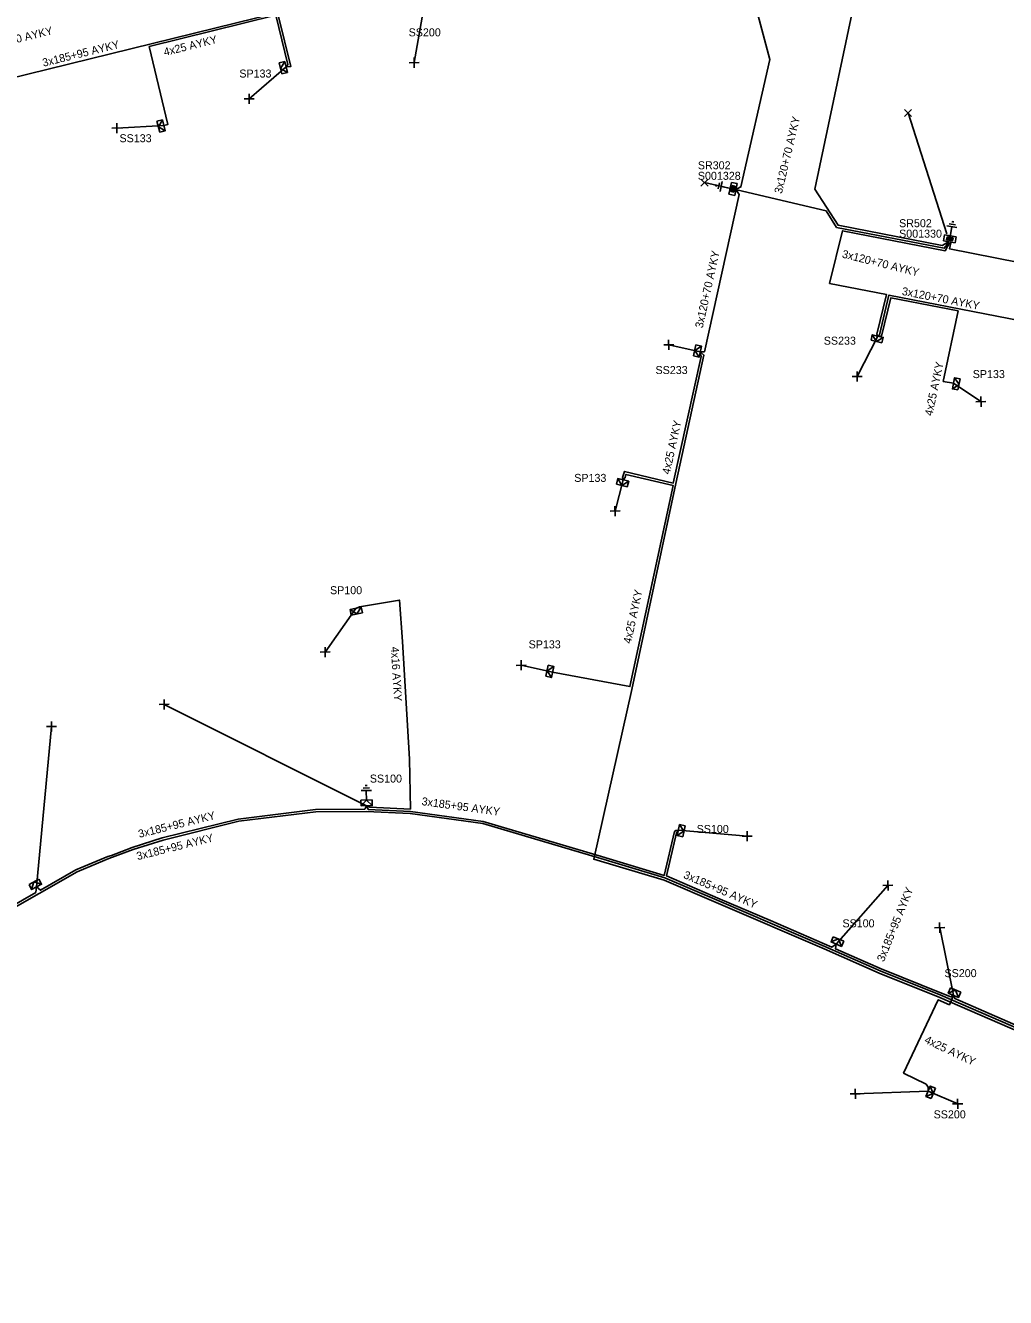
# Model space of a CAD drawing. Extents: x -762500 to -761285, y -1155006 to -1154135.
# Drawn here: x -762207.7 to -762085.9, y -1154817.7 to -1154659.6 of the extents above; entities that cross this region are included whole.
import ezdxf

# ---------------------------------------------------------------- set-up
doc = ezdxf.new("R2010")
doc.units = 0
for name, color, linetype in [('Vrstva 15', 7, 'Continuous'), ('Vrstva 28', 7, 'Continuous'), ('Vrstva 29', 7, 'Continuous'), ('Vrstva 30', 7, 'Continuous'), ('Vrstva 31', 7, 'Continuous'), ('Vrstva 33', 7, 'Continuous'), ('Vrstva 34', 7, 'Continuous'), ('Vrstva 5', 7, 'Continuous'), ('Vrstva 59', 7, 'Continuous'), ('Vrstva 6', 7, 'Continuous')]:
    doc.layers.add(name, color=color, linetype=linetype)

msp = doc.modelspace()

# ---------------------------------------------------------------- linework, layer by layer
at = {"layer": 'Vrstva 15'}
for points in [[(-762121.928, -1154679.632), (-762121.901, -1154679.502)], [(-762121.901, -1154679.502), (-762121.874, -1154679.376)], [(-762121.672, -1154679.943), (-762121.509, -1154679.172)], [(-762121.419, -1154680.243), (-762121.159, -1154679.02)], [(-762120.067, -1154679.891), (-762121.289, -1154679.632)], [(-762093.221, -1154684.529), (-762091.99, -1154684.746)], [(-762092.93, -1154684.266), (-762092.155, -1154684.402)], [(-762092.823, -1154685.869), (-762092.606, -1154684.638)], [(-762092.628, -1154683.999), (-762092.497, -1154684.022)], [(-762092.497, -1154684.022), (-762092.371, -1154684.044)], [(-762165.767, -1154754.397), (-762164.979, -1154754.383)], [(-762165.521, -1154754.078), (-762165.388, -1154754.075)], [(-762165.388, -1154754.075), (-762165.26, -1154754.073)], [(-762166.002, -1154754.711), (-762164.752, -1154754.689)], [(-762165.355, -1154755.95), (-762165.377, -1154754.7)]]:
    msp.add_lwpolyline(points, dxfattribs=at)
at = {"layer": 'Vrstva 28'}
for points in [[(-762120.015, -1154679.133), (-762120.327, -1154680.6)], [(-762119.907, -1154679.536), (-762120.062, -1154680.264)], [(-762120.062, -1154680.264), (-762119.692, -1154680.343)], [(-762119.281, -1154679.289), (-762120.015, -1154679.133)], [(-762119.871, -1154679.592), (-762120.006, -1154680.228)], [(-762120.006, -1154680.228), (-762119.729, -1154680.287)], [(-762119.835, -1154679.649), (-762119.95, -1154680.192)], [(-762119.95, -1154680.192), (-762119.765, -1154680.231)], [(-762119.538, -1154679.615), (-762119.907, -1154679.536)], [(-762119.798, -1154679.705), (-762119.894, -1154680.155)], [(-762119.894, -1154680.155), (-762119.802, -1154680.175)], [(-762119.594, -1154679.651), (-762119.871, -1154679.592)], [(-762119.761, -1154679.755), (-762119.839, -1154680.125)], [(-762119.65, -1154679.688), (-762119.835, -1154679.649)], [(-762119.802, -1154680.175), (-762119.706, -1154679.724)], [(-762119.706, -1154679.724), (-762119.798, -1154679.705)], [(-762119.765, -1154680.231), (-762119.65, -1154679.688)], [(-762119.729, -1154680.287), (-762119.594, -1154679.651)], [(-762119.692, -1154680.343), (-762119.538, -1154679.615)], [(-762119.593, -1154680.756), (-762119.281, -1154679.289)], [(-762120.327, -1154680.6), (-762119.593, -1154680.756)], [(-762093.541, -1154685.635), (-762093.671, -1154686.373)], [(-762093.671, -1154686.373), (-762092.194, -1154686.634)], [(-762092.064, -1154685.895), (-762093.541, -1154685.635)], [(-762093.196, -1154685.887), (-762093.261, -1154686.26)], [(-762093.261, -1154686.26), (-762092.528, -1154686.389)], [(-762093.157, -1154685.942), (-762093.206, -1154686.221)], [(-762093.206, -1154686.221), (-762092.567, -1154686.334)], [(-762092.463, -1154686.017), (-762093.196, -1154685.887)], [(-762092.517, -1154686.055), (-762093.157, -1154685.942)], [(-762093.119, -1154685.997), (-762093.152, -1154686.183)], [(-762093.152, -1154686.183), (-762092.605, -1154686.279)], [(-762092.572, -1154686.093), (-762093.119, -1154685.997)], [(-762093.081, -1154686.052), (-762093.097, -1154686.145)], [(-762093.097, -1154686.145), (-762092.643, -1154686.225)], [(-762092.627, -1154686.132), (-762093.081, -1154686.052)], [(-762092.676, -1154686.171), (-762093.048, -1154686.105)], [(-762092.643, -1154686.225), (-762092.627, -1154686.132)], [(-762092.605, -1154686.279), (-762092.572, -1154686.093)], [(-762092.567, -1154686.334), (-762092.517, -1154686.055)], [(-762092.528, -1154686.389), (-762092.463, -1154686.017)], [(-762092.194, -1154686.634), (-762092.064, -1154685.895)]]:
    msp.add_lwpolyline(points, dxfattribs=at)
at = {"layer": 'Vrstva 31'}
for points in [[(-762176.199, -1154664.278), (-762175.52, -1154664.108), (-762175.182, -1154665.467), (-762175.861, -1154665.636)], [(-762176.199, -1154664.278), (-762175.861, -1154665.636)], [(-762176.03, -1154664.957), (-762175.52, -1154664.108)], [(-762176.03, -1154664.957), (-762175.182, -1154665.467)], [(-762191.39, -1154671.528), (-762190.711, -1154671.358), (-762190.372, -1154672.717), (-762191.051, -1154672.886)], [(-762191.39, -1154671.528), (-762191.051, -1154672.886)], [(-762191.221, -1154672.207), (-762190.711, -1154671.358)], [(-762191.221, -1154672.207), (-762190.372, -1154672.717)], [(-762102.662, -1154698.755), (-762102.505, -1154698.073), (-762101.141, -1154698.388), (-762101.298, -1154699.07)], [(-762102.662, -1154698.755), (-762101.298, -1154699.07)], [(-762101.98, -1154698.912), (-762102.505, -1154698.073)], [(-762101.98, -1154698.912), (-762101.141, -1154698.388)], [(-762124.429, -1154699.337), (-762124.72, -1154700.706)], [(-762124.429, -1154699.337), (-762123.744, -1154699.483), (-762124.035, -1154700.852), (-762124.72, -1154700.706)], [(-762124.574, -1154700.022), (-762123.744, -1154699.483)], [(-762124.574, -1154700.022), (-762124.035, -1154700.852)], [(-762091.856, -1154704.923), (-762092.543, -1154704.79), (-762092.276, -1154703.416), (-762091.589, -1154703.549)], [(-762091.723, -1154704.236), (-762092.276, -1154703.416)], [(-762091.856, -1154704.923), (-762091.589, -1154703.549)], [(-762091.723, -1154704.236), (-762092.543, -1154704.79)], [(-762134.301, -1154716.62), (-762134.132, -1154715.941), (-762132.773, -1154716.279), (-762132.943, -1154716.958)], [(-762134.301, -1154716.62), (-762132.943, -1154716.958)], [(-762133.622, -1154716.789), (-762134.132, -1154715.941)], [(-762133.622, -1154716.789), (-762132.773, -1154716.279)], [(-762167.242, -1154732.901), (-762167.388, -1154732.216), (-762166.018, -1154731.925), (-762165.873, -1154732.61)], [(-762166.557, -1154732.756), (-762167.388, -1154732.216)], [(-762166.557, -1154732.756), (-762166.018, -1154731.925)], [(-762167.242, -1154732.901), (-762165.873, -1154732.61)], [(-762142.769, -1154739.147), (-762143.06, -1154740.516)], [(-762142.769, -1154739.147), (-762142.084, -1154739.293), (-762142.375, -1154740.662), (-762143.06, -1154740.516)], [(-762142.915, -1154739.832), (-762142.084, -1154739.293)], [(-762142.915, -1154739.832), (-762142.375, -1154740.662)], [(-762164.649, -1154755.878), (-762166.049, -1154755.902)], [(-762164.649, -1154755.878), (-762164.637, -1154756.578), (-762166.037, -1154756.602), (-762166.049, -1154755.902)], [(-762165.349, -1154755.89), (-762166.037, -1154756.602)], [(-762165.349, -1154755.89), (-762164.637, -1154756.578)], [(-762126.051, -1154760.454), (-762126.736, -1154760.308), (-762126.445, -1154758.939), (-762125.76, -1154759.084)], [(-762125.906, -1154759.769), (-762126.445, -1154758.939)], [(-762126.051, -1154760.454), (-762125.76, -1154759.084)], [(-762125.906, -1154759.769), (-762126.736, -1154760.308)], [(-762206.059, -1154765.742), (-762207.295, -1154766.399)], [(-762206.059, -1154765.742), (-762205.73, -1154766.36), (-762206.966, -1154767.017), (-762207.295, -1154766.399)], [(-762206.677, -1154766.07), (-762206.966, -1154767.017)], [(-762206.677, -1154766.07), (-762205.73, -1154766.36)], [(-762106.059, -1154773.43), (-762106.333, -1154774.074), (-762107.621, -1154773.527), (-762107.348, -1154772.883)], [(-762106.704, -1154773.157), (-762107.621, -1154773.527)], [(-762106.059, -1154773.43), (-762107.348, -1154772.883)], [(-762106.704, -1154773.157), (-762106.333, -1154774.074)], [(-762091.499, -1154779.78), (-762091.772, -1154780.424), (-762093.061, -1154779.877), (-762092.788, -1154779.233)], [(-762092.143, -1154779.507), (-762093.061, -1154779.877)], [(-762091.499, -1154779.78), (-762092.788, -1154779.233)], [(-762092.143, -1154779.507), (-762091.772, -1154780.424)], [(-762095.2, -1154793.001), (-762095.845, -1154792.727), (-762095.298, -1154791.439), (-762094.653, -1154791.712)], [(-762094.927, -1154792.357), (-762095.845, -1154792.727)], [(-762094.927, -1154792.357), (-762095.298, -1154791.439)], [(-762095.2, -1154793.001), (-762094.653, -1154791.712)]]:
    msp.add_lwpolyline(points, dxfattribs=at)
at = {"layer": 'Vrstva 34'}
for points in [[(-762160.065, -1154664.261), (-762158.815, -1154664.239)], [(-762159.429, -1154664.875), (-762159.451, -1154663.625)], [(-762180.565, -1154668.761), (-762179.315, -1154668.739)], [(-762179.929, -1154669.375), (-762179.951, -1154668.125)], [(-762098.502, -1154670.058), (-762097.618, -1154670.942)], [(-762098.502, -1154670.942), (-762097.618, -1154670.058)], [(-762197.005, -1154672.391), (-762195.755, -1154672.369)], [(-762196.369, -1154673.005), (-762196.391, -1154671.755)], [(-762123.792, -1154678.718), (-762122.908, -1154679.602)], [(-762123.792, -1154679.602), (-762122.908, -1154678.718)], [(-762128.425, -1154699.321), (-762127.175, -1154699.299)], [(-762127.789, -1154699.935), (-762127.811, -1154698.685)], [(-762105.005, -1154703.261), (-762103.755, -1154703.239)], [(-762104.369, -1154703.875), (-762104.391, -1154702.625)], [(-762089.625, -1154706.391), (-762088.375, -1154706.369)], [(-762088.989, -1154707.005), (-762089.011, -1154705.755)], [(-762134.459, -1154720.605), (-762134.481, -1154719.355)], [(-762135.095, -1154719.991), (-762133.845, -1154719.969)], [(-762170.489, -1154738.125), (-762170.511, -1154736.875)], [(-762171.125, -1154737.511), (-762169.875, -1154737.489)], [(-762146.129, -1154739.765), (-762146.151, -1154738.515)], [(-762146.765, -1154739.151), (-762145.515, -1154739.129)], [(-762190.489, -1154744.625), (-762190.511, -1154743.375)], [(-762191.125, -1154744.011), (-762189.875, -1154743.989)], [(-762205.125, -1154746.761), (-762203.875, -1154746.739)], [(-762204.489, -1154747.375), (-762204.511, -1154746.125)], [(-762118.685, -1154760.391), (-762117.435, -1154760.369)], [(-762118.049, -1154761.005), (-762118.071, -1154759.755)], [(-762101.185, -1154766.511), (-762099.935, -1154766.489)], [(-762100.549, -1154767.125), (-762100.571, -1154765.875)], [(-762094.755, -1154771.761), (-762093.505, -1154771.739)], [(-762094.119, -1154772.375), (-762094.141, -1154771.125)], [(-762105.245, -1154792.411), (-762103.995, -1154792.389)], [(-762104.609, -1154793.025), (-762104.631, -1154791.775)], [(-762092.515, -1154793.661), (-762091.265, -1154793.639)], [(-762091.879, -1154794.275), (-762091.901, -1154793.025)]]:
    msp.add_lwpolyline(points, dxfattribs=at)
at = {"layer": 'Vrstva 5'}
for points in [[(-762018.03, -1154646.45), (-762017.58, -1154646.23), (-762016.49, -1154646.47), (-762014.67, -1154637.34), (-762032.87, -1154633.54), (-762058.42, -1154628.52), (-762100.97, -1154638.95), (-762109.63, -1154679.98), (-762106.75, -1154684.45), (-762093.8, -1154686.97), (-762093.14, -1154686.59)], [(-762139.3, -1154653.19), (-762139.13, -1154652.68), (-762140.12, -1154649.04), (-762120.48, -1154644.08), (-762115.24, -1154663.87), (-762118.83, -1154679.7), (-762119.29, -1154679.92)], [(-762223.4, -1154669.64), (-762222.98, -1154669.48), (-762140.4, -1154649.15), (-762139.3, -1154653.19)], [(-762139.3, -1154653.19), (-762139.7, -1154652.86), (-762140.61, -1154649.51), (-762159.19, -1154654.08), (-762158.25, -1154657.62), (-762158.33, -1154657.9), (-762158.54, -1154657.7), (-762159.49, -1154654.13), (-762176.33, -1154658.33), (-762174.77, -1154664.73), (-762175.35, -1154664.79), (-762175.14, -1154664.47), (-762176.64, -1154658.36), (-762192.36, -1154662.25), (-762190.04, -1154671.92), (-762190.54, -1154672.04)], [(-762123.89, -1154700.17), (-762123.37, -1154700.17), (-762119.06, -1154680.65), (-762119.34, -1154680.18)], [(-762119.32, -1154680.05), (-762108.25, -1154682.68), (-762106.94, -1154684.72), (-762093.57, -1154687.32), (-762093.01, -1154686.61)], [(-762092.89, -1154686.64), (-762093.45, -1154687.65), (-762106.2, -1154685.14), (-762107.82, -1154691.68), (-762100.72, -1154693.07), (-762101.93, -1154697.99), (-762101.82, -1154698.24)], [(-762092.76, -1154686.66), (-762092.9, -1154687.39), (-762055.52, -1154694.77), (-762054.12, -1154687.55), (-762054.84, -1154687.45)], [(-762101.82, -1154698.24), (-762101.62, -1154698.07), (-762100.44, -1154693.13), (-762079.55, -1154697.2), (-762078.36, -1154697.42), (-762078.23, -1154698.37), (-762077.81, -1154697.52), (-762019.05, -1154708.75), (-762020.51, -1154715.85), (-762021.06, -1154716.05)], [(-762101.82, -1154698.24), (-762101.35, -1154698.23), (-762100.21, -1154693.48), (-762091.84, -1154695.11), (-762093.69, -1154703.86), (-762092.4, -1154704.1)], [(-762123.89, -1154700.17), (-762123.78, -1154700.77), (-762127.23, -1154716.5), (-762133.31, -1154715.06), (-762133.54, -1154715.82), (-762133.45, -1154716.11), (-762133.22, -1154715.82), (-762133.11, -1154715.42), (-762127.26, -1154716.79), (-762132.63, -1154741.8), (-762142.23, -1154739.98)], [(-762005.47, -1154815.51), (-762005.9, -1154815.54), (-762006.91, -1154817.72), (-762027.5, -1154808.79), (-762050.51, -1154798.85), (-762079.21, -1154786.89), (-762094.1, -1154780.44), (-762101.63, -1154777.4), (-762108.5, -1154774.39), (-762121.62, -1154768.73), (-762128.38, -1154765.83), (-762137.12, -1154763.24), (-762132.4, -1154742.15), (-762126.9, -1154716.57), (-762123.43, -1154700.6), (-762123.89, -1154700.17)], [(-762165.34, -1154756.59), (-762164.94, -1154756.76), (-762159.89, -1154757.01), (-762160.03, -1154750.83), (-762160.9, -1154736.18), (-762161.27, -1154731.03), (-762166.22, -1154731.88), (-762166.7, -1154732.07)], [(-762234.41, -1154785.99), (-762234.08, -1154785.6), (-762232.76, -1154782.95), (-762217.81, -1154773.87), (-762206.44, -1154767.37), (-762206.35, -1154766.69), (-762205.87, -1154767.1), (-762201.48, -1154764.57), (-762197.5, -1154762.89), (-762197.06, -1154762.77), (-762194.48, -1154761.79), (-762190.73, -1154760.6), (-762181.3, -1154758.26), (-762171.71, -1154757.08), (-762165.58, -1154757.01), (-762165.34, -1154756.59)], [(-762217.64, -1154774.11), (-762206.02, -1154767.5), (-762201.33, -1154764.82), (-762197.37, -1154763.14), (-762194.37, -1154762.05), (-762190.63, -1154760.87), (-762181.23, -1154758.53), (-762171.67, -1154757.36), (-762165.37, -1154757.31), (-762159.93, -1154757.58), (-762150.92, -1154758.82), (-762136.22, -1154763.17), (-762128.28, -1154765.54), (-762121.5, -1154768.45), (-762108.38, -1154774.11), (-762101.51, -1154777.12), (-762093.99, -1154780.16), (-762079.09, -1154786.61)], [(-762092.42, -1154780.15), (-762092.74, -1154780.36), (-762093.89, -1154779.91), (-762101.41, -1154776.87), (-762107.06, -1154774.39), (-762106.98, -1154773.8), (-762107.55, -1154774.19), (-762115.16, -1154770.87), (-762121.4, -1154768.2), (-762128.06, -1154765.31), (-762126.82, -1154759.96), (-762126.59, -1154759.62), (-762126.92, -1154759.66), (-762127.08, -1154759.78), (-762128.36, -1154765.25), (-762136.15, -1154762.91), (-762150.87, -1154758.55), (-762159.9, -1154757.31), (-762165.13, -1154757.05), (-762165.34, -1154756.59)], [(-762092.42, -1154780.15), (-762092.92, -1154781.33), (-762094.3, -1154780.71), (-762098.62, -1154789.83), (-762095.81, -1154791.18), (-762095.55, -1154791.57), (-762095.57, -1154792.08)], [(-762062.28, -1154792.91), (-762062.72, -1154793.16), (-762078.79, -1154786.45), (-762078.83, -1154785.97), (-762079.16, -1154786.28), (-762092.24, -1154780.56), (-762092.42, -1154780.15)]]:
    msp.add_lwpolyline(points, dxfattribs=at)
at = {"layer": 'Vrstva 59'}
for points in [[(-762158.33, -1154657.9), (-762159.44, -1154664.25)], [(-762175.35, -1154664.79), (-762179.94, -1154668.75)], [(-762093.23, -1154685.54), (-762098.06, -1154670.5)], [(-762190.54, -1154672.04), (-762196.38, -1154672.38)], [(-762120.3, -1154679.83), (-762123.35, -1154679.16)], [(-762123.89, -1154700.17), (-762127.8, -1154699.31)], [(-762101.82, -1154698.24), (-762104.38, -1154703.25)], [(-762092.41, -1154704.1), (-762089, -1154706.38)], [(-762133.45, -1154716.11), (-762134.47, -1154719.98)], [(-762166.7, -1154732.07), (-762170.5, -1154737.5)], [(-762142.23, -1154739.98), (-762146.14, -1154739.14)], [(-762165.34, -1154756.59), (-762190.5, -1154744)], [(-762206.35, -1154766.69), (-762204.5, -1154746.75)], [(-762126.59, -1154759.62), (-762118.06, -1154760.38)], [(-762106.98, -1154773.8), (-762100.56, -1154766.5)], [(-762092.42, -1154780.15), (-762094.13, -1154771.75)], [(-762095.57, -1154792.08), (-762104.62, -1154792.4)], [(-762095.57, -1154792.08), (-762091.89, -1154793.65)]]:
    msp.add_lwpolyline(points, dxfattribs=at)

# ---------------------------------------------------------------- texts
at = {"layer": 'Vrstva 29'}
for s, p in [('S001328', (-762124.18, -1154678.81)), ('S001330', (-762099.17, -1154686))]:
    msp.add_text(s, height=0.9943, dxfattribs=at).set_placement(p)
at = {"layer": 'Vrstva 30'}
for s, p in [('SR302', (-762124.18, -1154677.5)), ('SR502', (-762099.17, -1154684.7))]:
    msp.add_text(s, height=0.9943, dxfattribs=at).set_placement(p)
at = {"layer": 'Vrstva 33'}
for s, p in [('SS200', (-762160.12, -1154660.98)), ('SP133', (-762181.16, -1154666.1)), ('SS133', (-762196.05, -1154674.14)), ('SS233', (-762108.53, -1154699.3)), ('SS233', (-762129.44, -1154702.95)), ('SP133', (-762090.02, -1154703.45)), ('SP133', (-762139.54, -1154716.35)), ('SP100', (-762169.89, -1154730.31)), ('SP133', (-762145.21, -1154737.04)), ('SS100', (-762164.94, -1154753.72)), ('SS100', (-762124.33, -1154759.98)), ('SS100', (-762106.21, -1154771.71)), ('SS200', (-762093.53, -1154777.9)), ('SS200', (-762094.88, -1154795.45))]:
    msp.add_text(s, height=0.9943, dxfattribs=at).set_placement(p)
at = {"layer": 'Vrstva 6'}
for s, height, rotation, p in [('3x120+70 AYKY', 0.99429, 13.78703, (-762213.79, -1154663.04)), ('4x25 AYKY', 0.9943, 13.89643, (-762190.43, -1154663.43)), ('3x185+95 AYKY', 0.99429, 13.83593, (-762205.5, -1154664.76)), ('3x120+70 AYKY', 0.99429, 76.64142, (-762113.74, -1154680.6)), ('3x120+70 AYKY', 0.99429, 77.53212, (-762123.58, -1154697.31)), ('3x120+70 AYKY', 0.99428, 346.03799, (-762106.33, -1154688.46)), ('3x120+70 AYKY', 0.99429, 348.98993, (-762098.89, -1154693.1)), ('4x25 AYKY', 0.9943, 78.10705, (-762095.04, -1154708.21)), ('4x25 AYKY', 0.9943, 77.62246, (-762127.67, -1154715.48)), ('4x25 AYKY', 0.9943, 77.86534, (-762132.49, -1154736.52)), ('4x16 AYKY', 0.9943, 273.39856, (-762162.33, -1154736.86)), ('3x185+95 AYKY', 0.99429, 352.18104, (-762158.55, -1154756.51)), ('3x185+95 AYKY', 0.99429, 13.93613, (-762193.58, -1154760.6)), ('3x185+95 AYKY', 0.99428, 13.9344, (-762193.8, -1154763.37)), ('3x185+95 AYKY', 0.99428, 336.83466, (-762126.06, -1154765.55)), ('3x185+95 AYKY', 0.99429, 67.98872, (-762101.06, -1154776.06)), ('4x25 AYKY', 0.9943, 334.65598, (-762096.11, -1154786.02))]:
    msp.add_text(s, height=height, rotation=rotation, dxfattribs=at).set_placement(p)

doc.saveas('drawing.dxf')
